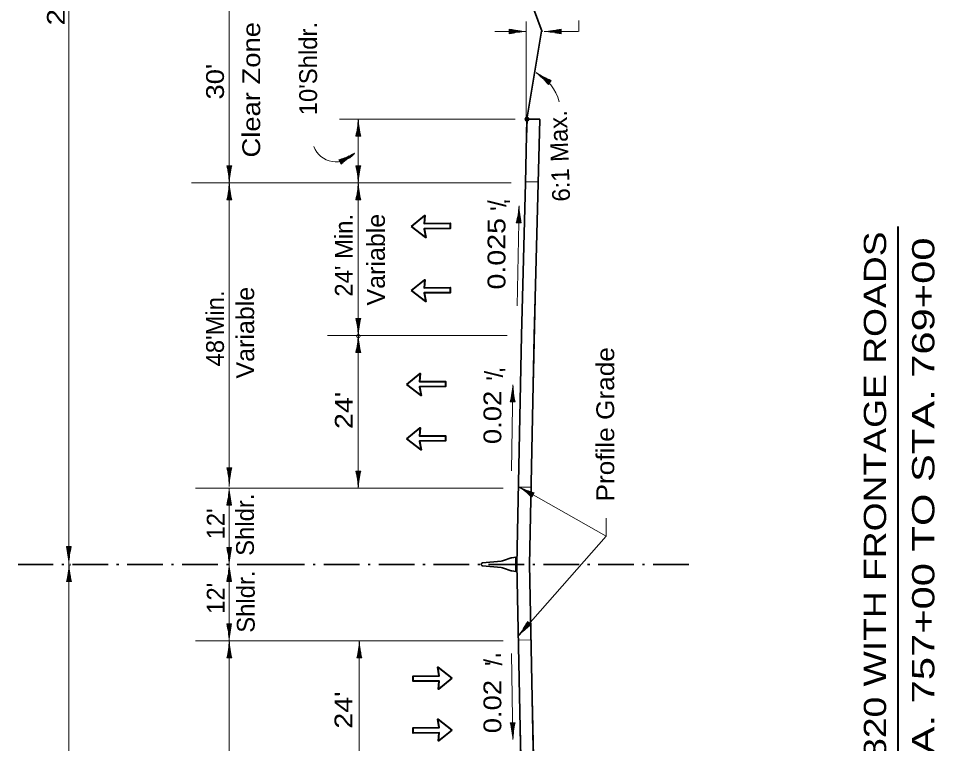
# Model space of a CAD drawing. Extents: x 2363427 to 2368559, y 6957299 to 6980140.
# Drawn here: x 2364656 to 2365376, y 6958931 to 6959501 of the extents above; entities that cross this region are included whole.
import ezdxf
from ezdxf.enums import TextEntityAlignment as Align

# ---------------------------------------------------------------- set-up
doc = ezdxf.new("R2010")
doc.units = 0
doc.header["$LTSCALE"] = 5.6
doc.header["$PDMODE"] = 32
doc.header["$PDSIZE"] = 2.8
doc.linetypes.add('DOT_DASHED', pattern=[7.7, 5, -1.2, 0.3, -1.2])
doc.linetypes.add('LONG_DASHED', pattern=[7.5, 6, -1.5])
for name, color, linetype, lineweight in [('1', 7, 'Continuous', 13), ('3', 7, 'Continuous', 35), ('4', 7, 'Continuous', 13), ('40', 7, 'Continuous', 35), ('6', 7, 'Continuous', 13), ('8', 7, 'Continuous', 13)]:
    doc.layers.add(name, color=color, linetype=linetype, lineweight=lineweight)

msp = doc.modelspace()

# ---------------------------------------------------------------- linework, layer by layer
at = {"layer": '1', "linetype": 'LONG_DASHED'}
msp.add_line((2365055.414, 6959421.319), (2365055.653, 6959421.417), dxfattribs=at)
at = {"layer": '3'}
for p, q in [((2364963.114, 6959774.14), (2365067.63, 6959490.027)), ((2365065.653, 6959421.301), (2365056.156, 6959421.301)), ((2365064.481, 6959371.033), (2365065.65, 6959421.184)), ((2365061.348, 6959251.139), (2365064.48, 6959371.005)), ((2365047.761, 6959071.447), (2365051.351, 6959251.401)), ((2365057.76, 6959071.247), (2365061.35, 6959251.201)), ((2365035.48, 6959074.019), (2365020.776, 6959072.783)), ((2365037.268, 6959074.547), (2365043.382, 6959076.589)), ((2365043.546, 6959076.654), (2365043.556, 6959076.679)), ((2365046.819, 6959077.167), (2365043.556, 6959076.679)), ((2365046.819, 6959077.167), (2365043.753, 6959076.708)), ((2365046.819, 6959077.167), (2365046.819, 6959071.542)), ((2365019.749, 6959071.943), (2365019.749, 6959071.542)), ((2365019.749, 6959071.141), (2365019.749, 6959071.542)), ((2365035.48, 6959069.065), (2365020.776, 6959070.301)), ((2365037.268, 6959068.537), (2365043.382, 6959066.495)), ((2365043.546, 6959066.43), (2365043.556, 6959066.405)), ((2365046.819, 6959065.917), (2365043.556, 6959066.405)), ((2365046.819, 6959065.917), (2365043.753, 6959066.376)), ((2365046.819, 6959065.917), (2365046.819, 6959071.542)), ((2365057.76, 6959071.646), (2365061.35, 6958891.693))]:
    msp.add_line(p, q, dxfattribs=at)
at = {"layer": '3', "lineweight": 13}
for p, q in [((2365067.381, 6959491.559), (2365067.088, 6959490.537)), ((2365046.336, 6959421.447), (2364908.326, 6959421.447)), ((2365043.199, 6959371.447), (2364792.272, 6959371.447)), ((2365040.062, 6959251.447), (2364898.916, 6959251.447)), ((2365036.926, 6959131.447), (2364795.41, 6959131.447)), ((2365036.926, 6959011.447), (2364795.41, 6959011.447))]:
    msp.add_line(p, q, dxfattribs=at)
at = {"layer": '3', "linetype": 'DOT_DASHED'}
for p, q in [((2364855.959, 6959071.447), (2364656.146, 6959071.447)), ((2365182.836, 6959071.447), (2364854.258, 6959071.447))]:
    msp.add_line(p, q, dxfattribs=at)
at = {"layer": '3'}
for points in [[(2365051.351, 6959251.401), (2365054.484, 6959371.267), (2365055.653, 6959421.417), (2365067.088, 6959490.537)], [(2365047.761, 6959071.447), (2365051.351, 6958891.493), (2365054.484, 6958771.627)]]:
    msp.add_lwpolyline(points, dxfattribs=at)
at = {"layer": '3', "lineweight": 13}
for points in [[(2365054.285, 6959372.289), (2365064.582, 6959372.289), (2365065.653, 6959421.301), (2365056.156, 6959421.301)], [(2365049, 6959132.219), (2365058.916, 6959132.218), (2365064.582, 6959372.289), (2365054.285, 6959372.289)], [(2365048.975, 6959011.836), (2365047.721, 6959071.764), (2365049, 6959132.219), (2365058.916, 6959132.218), (2365057.541, 6959071.372), (2365058.919, 6959012.302)], [(2365054.483, 6958770.888), (2365064.398, 6958771.059), (2365058.919, 6959012.302), (2365048.975, 6959011.836)]]:
    msp.add_lwpolyline(points, close=True, dxfattribs=at)
at = {"layer": '3'}
for centre, radius, start, end in [((2365034.98, 6959078.994), 5, 275.73538, 297.22872), ((2365043.93, 6959075.522), 1.2, 98.51269, 117.22516), ((2365020.896, 6959071.59), 1.2, 95.72178, 162.90786), ((2365020.896, 6959071.494), 1.2, 197.09214, 264.27822), ((2365034.98, 6959064.09), 5, 62.77128, 84.26462), ((2365043.93, 6959067.562), 1.2, 242.77484, 261.48731)]:
    msp.add_arc(centre, radius, start, end, dxfattribs=at)
msp.add_point((2365055.653, 6959421.417), dxfattribs=at)
at = {"layer": '4'}
for p, q in [((2365055.102, 6959420.827), (2365055.102, 6959498.291)), ((2365096.47, 6959490.379), (2365096.47, 6959499.023)), ((2365041.791, 6959488.411), (2365041.791, 6959492.241)), ((2365041.791, 6959491.761), (2365044.172, 6959491.761)), ((2365041.791, 6959491.261), (2365046.653, 6959491.261)), ((2365041.791, 6959490.761), (2365050.4, 6959490.761)), ((2365082.53, 6959490.891), (2365075.18, 6959490.891)), ((2365082.53, 6959491.391), (2365078.253, 6959491.391)), ((2365082.53, 6959491.891), (2365080.944, 6959491.891)), ((2365082.53, 6959492.241), (2365082.53, 6959488.411)), ((2365055.102, 6959490.327), (2365030.4, 6959490.327)), ((2365041.791, 6959490.261), (2365054.355, 6959490.261)), ((2365041.791, 6959489.761), (2365049.141, 6959489.761)), ((2365041.791, 6959489.261), (2365046.068, 6959489.261)), ((2365041.791, 6959488.761), (2365043.376, 6959488.761)), ((2365069.218, 6959490.327), (2365095.796, 6959490.327)), ((2365082.53, 6959490.391), (2365069.966, 6959490.391)), ((2365082.53, 6959489.891), (2365073.92, 6959489.891)), ((2365082.53, 6959489.391), (2365077.668, 6959489.391)), ((2365082.53, 6959488.891), (2365080.148, 6959488.891)), ((2365073.662, 6959450.405), (2365063.421, 6959457.685)), ((2365073.372, 6959449.997), (2365066.355, 6959454.985)), ((2365073.952, 6959450.813), (2365067.961, 6959455.071)), ((2365073.082, 6959449.589), (2365069.12, 6959452.407)), ((2365074.241, 6959451.221), (2365070.756, 6959453.697)), ((2365072.793, 6959449.183), (2365070.852, 6959450.563)), ((2365074.734, 6959451.913), (2365072.515, 6959448.791)), ((2365074.531, 6959451.627), (2365073.239, 6959452.545)), ((2364908.086, 6959388.925), (2364910.122, 6959390.161)), ((2364908.346, 6959388.497), (2364912.502, 6959391.019)), ((2364908.605, 6959388.069), (2364915.964, 6959392.537)), ((2364908.864, 6959387.643), (2364919.605, 6959394.161)), ((2364909.124, 6959387.215), (2364915.406, 6959391.029)), ((2364909.824, 6959386.061), (2364907.837, 6959389.335)), ((2364909.384, 6959386.787), (2364913.04, 6959389.007)), ((2364909.643, 6959386.361), (2364910.998, 6959387.183)), ((2365049.461, 6959353.273), (2365047.85, 6959274.651)), ((2365048.624, 6959339.975), (2365048.774, 6959347.323)), ((2365049.123, 6959339.965), (2365049.38, 6959352.527)), ((2365049.623, 6959339.955), (2365049.8, 6959348.563)), ((2365047.274, 6959340.003), (2365051.103, 6959339.925)), ((2365047.624, 6959339.995), (2365047.656, 6959341.581)), ((2365048.124, 6959339.985), (2365048.211, 6959344.261)), ((2365050.123, 6959339.945), (2365050.222, 6959344.805)), ((2365050.623, 6959339.935), (2365050.672, 6959342.315)), ((2365044.629, 6959212.673), (2365043.555, 6959144.957)), ((2365044.353, 6959199.365), (2365044.552, 6959211.927)), ((2365043.353, 6959199.381), (2365043.421, 6959203.657)), ((2365043.853, 6959199.373), (2365043.97, 6959206.721)), ((2365044.853, 6959199.357), (2365044.99, 6959207.965)), ((2365045.352, 6959199.349), (2365045.43, 6959204.211)), ((2365042.503, 6959199.395), (2365046.332, 6959199.333)), ((2365042.853, 6959199.389), (2365042.878, 6959200.973)), ((2365045.852, 6959199.341), (2365045.89, 6959201.723)), ((2365117.773, 6959093.806), (2365048.984, 6959132.754)), ((2365060.413, 6959125.928), (2365049.595, 6959132.317)), ((2365060.667, 6959126.359), (2365053.254, 6959130.737)), ((2365060.158, 6959125.498), (2365053.83, 6959129.235)), ((2365059.904, 6959125.067), (2365056.222, 6959127.242)), ((2365060.922, 6959126.789), (2365056.735, 6959129.262)), ((2365059.65, 6959124.637), (2365058.286, 6959125.442)), ((2365061.176, 6959127.22), (2365059.125, 6959128.432)), ((2365059.471, 6959124.336), (2365061.42, 6959127.633)), ((2365117.773, 6959107.72), (2365117.773, 6959093.806)), ((2365117.773, 6959093.806), (2365048.882, 6959015.234)), ((2365057.505, 6959025.376), (2365049.414, 6959015.764)), ((2365057.122, 6959025.698), (2365051.578, 6959019.111)), ((2365057.887, 6959025.053), (2365053.155, 6959019.431)), ((2365056.74, 6959026.02), (2365053.608, 6959022.3)), ((2365056.357, 6959026.342), (2365054.823, 6959024.52)), ((2365058.27, 6959024.731), (2365055.516, 6959021.46)), ((2365058.92, 6959024.183), (2365055.99, 6959026.651)), ((2365058.652, 6959024.409), (2365057.632, 6959023.197)), ((2365044.629, 6958933.771), (2365043.555, 6959001.489)), ((2365042.503, 6958947.051), (2365046.332, 6958947.111)), ((2365042.853, 6958947.057), (2365042.878, 6958945.471)), ((2365043.353, 6958947.065), (2365043.421, 6958942.789)), ((2365043.853, 6958947.073), (2365043.97, 6958939.723)), ((2365044.353, 6958947.081), (2365044.552, 6958934.517)), ((2365044.853, 6958947.089), (2365044.99, 6958938.479)), ((2365045.352, 6958947.097), (2365045.43, 6958942.235)), ((2365045.852, 6958947.105), (2365045.89, 6958944.723))]:
    msp.add_line(p, q, dxfattribs=at)
at = {"layer": '4', "lineweight": 40}
msp.add_line((2365347.244, 6958874.931), (2365347.244, 6959337.074), dxfattribs=at)
at = {"layer": '4'}
for centre, radius, start, end in [((2365058.685, 6959562.45), 72.212, 256.47039, 267.15644), ((2365065.636, 6959562.45), 72.212, 272.84356, 283.52961), ((2365058.685, 6959418.203), 72.212, 92.84356, 103.52961), ((2365065.636, 6959418.203), 72.212, 76.47039, 87.15644), ((2365046.984, 6959426.793), 34.94, 13.44028, 63.14536), ((2365101.642, 6959518.925), 72.212, 237.43652, 248.12257), ((2365018.068, 6959401.355), 72.212, 41.06336, 51.74941), ((2364905.832, 6959406.596), 18.823, 200.84978, 319.74384), ((2364885.845, 6959458.117), 72.212, 287.73061, 298.41666), ((2364960.699, 6959334.812), 72.212, 124.10378, 134.78983), ((2364977.426, 6959358.331), 72.212, 345.29652, 355.98257), ((2365121.643, 6959355.376), 72.212, 181.66968, 192.35573), ((2364972.571, 6959217.399), 72.212, 345.56175, 356.2478), ((2365116.8, 6959215.112), 72.212, 181.93492, 192.62097), ((2365082.578, 6959196.676), 72.212, 242.27611, 252.96216), ((2365009.221, 6959072.475), 72.212, 45.90294, 56.58899), ((2364991.401, 6959058.944), 72.212, 322.74962, 333.43567), ((2365101.749, 6958966.043), 72.212, 126.37646, 137.06251), ((2364972.571, 6958929.046), 72.212, 3.7522, 14.43825), ((2365116.8, 6958931.333), 72.212, 167.37903, 178.06508)]:
    msp.add_arc(centre, radius, start, end, dxfattribs=at)
at = {"layer": '40'}
for p, q in [((2364974.856, 6959339.363), (2364995.36, 6959339.557)), ((2364974.856, 6959288.911), (2364995.36, 6959289.106)), ((2364971.216, 6959215.175), (2364991.721, 6959215.369)), ((2364971.216, 6959172.485), (2364991.721, 6959172.68)), ((2364986.774, 6958979.863), (2364966.27, 6958979.667)), ((2364986.774, 6958939.113), (2364966.27, 6958938.919))]:
    msp.add_line(p, q, dxfattribs=at)
for points in [[(2364974.856, 6959339.363), (2364975.388, 6959345.677), (2364965, 6959337.143), (2364976.1, 6959328.54), (2364974.893, 6959335.267)], [(2364974.893, 6959335.267), (2364995.398, 6959335.463), (2364995.36, 6959339.557)], [(2364974.856, 6959288.911), (2364975.388, 6959295.226), (2364965, 6959286.691), (2364976.1, 6959278.089), (2364974.893, 6959284.816)], [(2364974.893, 6959284.816), (2364995.398, 6959285.011), (2364995.36, 6959289.106)], [(2364971.216, 6959215.175), (2364971.748, 6959221.489), (2364961.361, 6959212.955), (2364972.461, 6959204.352), (2364971.254, 6959211.079)], [(2364971.254, 6959211.079), (2364991.758, 6959211.275), (2364991.721, 6959215.369)], [(2364971.216, 6959172.485), (2364971.748, 6959178.8), (2364961.361, 6959170.265), (2364972.461, 6959161.663), (2364971.254, 6959168.39)], [(2364971.254, 6959168.39), (2364991.758, 6959168.585), (2364991.721, 6959172.68)], [(2364986.774, 6958979.863), (2364986.242, 6958973.547), (2364996.63, 6958982.083), (2364985.53, 6958990.685), (2364986.737, 6958983.957)], [(2364986.737, 6958983.957), (2364966.232, 6958983.763), (2364966.27, 6958979.667)], [(2364986.774, 6958939.113), (2364986.242, 6958932.799), (2364996.63, 6958941.333), (2364985.53, 6958949.936), (2364986.737, 6958943.209)], [(2364986.737, 6958943.209), (2364966.232, 6958943.013), (2364966.27, 6958938.919)]]:
    msp.add_lwpolyline(points, dxfattribs=at)
at = {"layer": '6'}
for p, q in [((2364695.798, 6959070.731), (2364695.798, 6960071.447)), ((2364923.238, 6959408.135), (2364923.238, 6959420.699)), ((2364922.238, 6959408.135), (2364922.238, 6959412.997)), ((2364922.738, 6959408.135), (2364922.738, 6959416.745)), ((2364923.738, 6959408.135), (2364923.738, 6959415.485)), ((2364924.238, 6959408.135), (2364924.238, 6959412.411)), ((2364925.088, 6959408.135), (2364921.258, 6959408.135)), ((2364921.738, 6959408.135), (2364921.738, 6959410.517)), ((2364924.738, 6959408.135), (2364924.738, 6959409.72)), ((2364819.941, 6959384.73), (2364823.771, 6959384.73)), ((2364820.291, 6959384.73), (2364820.291, 6959383.145)), ((2364820.791, 6959384.73), (2364820.791, 6959380.453)), ((2364821.291, 6959384.73), (2364821.291, 6959377.38)), ((2364821.791, 6959384.73), (2364821.791, 6959372.166)), ((2364822.291, 6959384.73), (2364822.291, 6959376.121)), ((2364822.791, 6959384.73), (2364822.791, 6959379.868)), ((2364823.291, 6959384.73), (2364823.291, 6959382.349)), ((2364921.258, 6959384.73), (2364925.088, 6959384.73)), ((2364921.608, 6959384.73), (2364921.608, 6959383.145)), ((2364922.108, 6959384.73), (2364922.108, 6959380.453)), ((2364922.608, 6959384.73), (2364922.608, 6959377.38)), ((2364923.108, 6959384.73), (2364923.108, 6959372.166)), ((2364923.608, 6959384.73), (2364923.608, 6959376.121)), ((2364924.108, 6959384.73), (2364924.108, 6959379.868)), ((2364924.608, 6959384.73), (2364924.608, 6959382.349)), ((2364821.921, 6959358.107), (2364821.921, 6959370.671)), ((2364923.238, 6959358.107), (2364923.238, 6959370.671)), ((2364820.921, 6959358.107), (2364820.921, 6959362.969)), ((2364821.421, 6959358.107), (2364821.421, 6959366.717)), ((2364822.421, 6959358.107), (2364822.421, 6959365.457)), ((2364822.921, 6959358.107), (2364822.921, 6959362.383)), ((2364922.238, 6959358.107), (2364922.238, 6959362.969)), ((2364922.738, 6959358.107), (2364922.738, 6959366.717)), ((2364923.738, 6959358.107), (2364923.738, 6959365.457)), ((2364924.238, 6959358.107), (2364924.238, 6959362.383)), ((2364823.771, 6959358.107), (2364819.941, 6959358.107)), ((2364820.421, 6959358.107), (2364820.421, 6959360.489)), ((2364823.421, 6959358.107), (2364823.421, 6959359.692)), ((2364925.088, 6959358.107), (2364921.258, 6959358.107)), ((2364921.738, 6959358.107), (2364921.738, 6959360.489)), ((2364924.738, 6959358.107), (2364924.738, 6959359.692)), ((2364921.258, 6959264.758), (2364925.088, 6959264.758)), ((2364921.608, 6959264.758), (2364921.608, 6959263.173)), ((2364922.108, 6959264.758), (2364922.108, 6959260.481)), ((2364922.608, 6959264.758), (2364922.608, 6959257.408)), ((2364923.108, 6959264.758), (2364923.108, 6959252.194)), ((2364923.608, 6959264.758), (2364923.608, 6959256.149)), ((2364924.108, 6959264.758), (2364924.108, 6959259.896)), ((2364924.608, 6959264.758), (2364924.608, 6959262.377)), ((2364922.738, 6959238.135), (2364922.738, 6959246.745)), ((2364923.173, 6959252.075), (2364923.173, 6959252.705)), ((2364923.173, 6959131.503), (2364923.173, 6959251.447)), ((2364923.238, 6959238.135), (2364923.238, 6959250.699)), ((2364921.738, 6959238.135), (2364921.738, 6959240.517)), ((2364922.238, 6959238.135), (2364922.238, 6959242.997)), ((2364923.738, 6959238.135), (2364923.738, 6959245.485)), ((2364924.238, 6959238.135), (2364924.238, 6959242.411)), ((2364924.738, 6959238.135), (2364924.738, 6959239.72)), ((2364925.088, 6959238.135), (2364921.258, 6959238.135)), ((2364819.941, 6959147.33), (2364823.771, 6959147.33)), ((2364820.291, 6959147.33), (2364820.291, 6959145.745)), ((2364820.791, 6959147.33), (2364820.791, 6959143.053)), ((2364821.291, 6959147.33), (2364821.291, 6959139.98)), ((2364821.791, 6959147.33), (2364821.791, 6959134.766)), ((2364822.291, 6959147.33), (2364822.291, 6959138.721)), ((2364822.791, 6959147.33), (2364822.791, 6959142.468)), ((2364823.291, 6959147.33), (2364823.291, 6959144.949)), ((2364921.258, 6959144.814), (2364925.088, 6959144.814)), ((2364921.608, 6959144.814), (2364921.608, 6959143.229)), ((2364922.108, 6959144.814), (2364922.108, 6959140.537)), ((2364922.608, 6959144.814), (2364922.608, 6959137.464)), ((2364923.108, 6959144.814), (2364923.108, 6959132.25)), ((2364923.608, 6959144.814), (2364923.608, 6959136.205)), ((2364924.108, 6959144.814), (2364924.108, 6959139.952)), ((2364924.608, 6959144.814), (2364924.608, 6959142.433)), ((2364821.856, 6959132.733), (2364821.856, 6959134.019)), ((2364821.332, 6959118.135), (2364821.332, 6959126.745)), ((2364821.832, 6959118.135), (2364821.832, 6959130.699)), ((2364822.332, 6959118.135), (2364822.332, 6959125.485)), ((2364823.682, 6959118.135), (2364819.852, 6959118.135)), ((2364820.332, 6959118.135), (2364820.332, 6959120.517)), ((2364820.832, 6959118.135), (2364820.832, 6959122.997)), ((2364822.832, 6959118.135), (2364822.832, 6959122.411)), ((2364823.332, 6959118.135), (2364823.332, 6959119.721)), ((2364693.882, 6959085.449), (2364697.712, 6959085.449)), ((2364694.232, 6959085.449), (2364694.232, 6959083.863)), ((2364694.732, 6959085.449), (2364694.732, 6959081.173)), ((2364695.232, 6959085.449), (2364695.232, 6959078.099)), ((2364695.732, 6959085.449), (2364695.732, 6959072.885)), ((2364696.232, 6959085.449), (2364696.232, 6959076.839)), ((2364696.732, 6959085.449), (2364696.732, 6959080.587)), ((2364697.232, 6959085.449), (2364697.232, 6959083.067)), ((2364819.852, 6959084.759), (2364823.682, 6959084.759)), ((2364820.202, 6959084.759), (2364820.202, 6959083.173)), ((2364820.702, 6959084.759), (2364820.702, 6959080.481)), ((2364821.202, 6959084.759), (2364821.202, 6959077.409)), ((2364821.702, 6959084.759), (2364821.702, 6959072.195)), ((2364822.202, 6959084.759), (2364822.202, 6959076.149)), ((2364822.702, 6959084.759), (2364822.702, 6959079.897)), ((2364823.202, 6959084.759), (2364823.202, 6959082.377)), ((2364695.498, 6959058.135), (2364695.498, 6959066.745)), ((2364695.934, 6958071.447), (2364695.934, 6959071.447)), ((2364695.998, 6959058.135), (2364695.998, 6959070.699)), ((2364696.784, 6959070.731), (2364696.784, 6959071.843)), ((2364821.332, 6959058.135), (2364821.332, 6959066.745)), ((2364821.832, 6959058.135), (2364821.832, 6959070.699)), ((2364694.498, 6959058.135), (2364694.498, 6959060.517)), ((2364694.998, 6959058.135), (2364694.998, 6959062.997)), ((2364696.498, 6959058.135), (2364696.498, 6959065.485)), ((2364696.998, 6959058.135), (2364696.998, 6959062.411)), ((2364697.498, 6959058.135), (2364697.498, 6959059.72)), ((2364820.332, 6959058.135), (2364820.332, 6959060.517)), ((2364820.832, 6959058.135), (2364820.832, 6959062.997)), ((2364822.332, 6959058.135), (2364822.332, 6959065.485)), ((2364822.832, 6959058.135), (2364822.832, 6959062.411)), ((2364823.332, 6959058.135), (2364823.332, 6959059.721)), ((2364697.848, 6959058.135), (2364694.018, 6959058.135)), ((2364823.682, 6959058.135), (2364819.852, 6959058.135)), ((2364819.852, 6959024.759), (2364823.682, 6959024.759)), ((2364820.202, 6959024.759), (2364820.202, 6959023.173)), ((2364820.702, 6959024.759), (2364820.702, 6959020.481)), ((2364821.202, 6959024.759), (2364821.202, 6959017.409)), ((2364821.702, 6959024.759), (2364821.702, 6959012.195)), ((2364822.202, 6959024.759), (2364822.202, 6959016.149)), ((2364822.702, 6959024.759), (2364822.702, 6959019.897)), ((2364823.202, 6959024.759), (2364823.202, 6959022.377)), ((2364821.862, 6958771.425), (2364821.862, 6959011.447)), ((2364821.927, 6958998.135), (2364821.927, 6959010.699)), ((2364923.994, 6958782.647), (2364923.994, 6959011.447)), ((2364924.06, 6958998.135), (2364924.06, 6959010.699)), ((2364820.927, 6958998.135), (2364820.927, 6959002.997)), ((2364821.427, 6958998.135), (2364821.427, 6959006.745)), ((2364822.427, 6958998.135), (2364822.427, 6959005.485)), ((2364822.927, 6958998.135), (2364822.927, 6959002.411)), ((2364923.06, 6958998.135), (2364923.06, 6959002.997)), ((2364923.56, 6958998.135), (2364923.56, 6959006.745)), ((2364924.56, 6958998.135), (2364924.56, 6959005.485)), ((2364925.06, 6958998.135), (2364925.06, 6959002.411)), ((2364823.777, 6958998.135), (2364819.947, 6958998.135)), ((2364820.427, 6958998.135), (2364820.427, 6959000.517)), ((2364823.427, 6958998.135), (2364823.427, 6958999.72)), ((2364925.91, 6958998.135), (2364922.08, 6958998.135)), ((2364922.56, 6958998.135), (2364922.56, 6959000.517)), ((2364925.56, 6958998.135), (2364925.56, 6958999.72))]:
    msp.add_line(p, q, dxfattribs=at)
for points in [[(2364821.856, 6959134.019), (2364821.856, 6959371.419), (2364821.856, 6959521.447)], [(2364923.173, 6959250.845), (2364923.173, 6959251.447), (2364923.173, 6959371.419), (2364923.173, 6959421.447)], [(2364821.767, 6959011.447), (2364821.767, 6959071.447), (2364821.767, 6959131.447)]]:
    msp.add_lwpolyline(points, dxfattribs=at)
for centre, start, end in [((2364851.049, 6959425.029), 346.47039, 357.15644), ((2364995.297, 6959425.029), 182.84356, 193.52961), ((2364749.732, 6959367.836), 2.84356, 13.52961), ((2364893.98, 6959367.836), 166.47039, 177.15644), ((2364851.049, 6959367.836), 2.84356, 13.52961), ((2364995.297, 6959367.836), 166.47039, 177.15644), ((2364749.732, 6959375.001), 346.47039, 357.15644), ((2364893.98, 6959375.001), 182.84356, 193.52961), ((2364851.049, 6959375.001), 346.47039, 357.15644), ((2364995.297, 6959375.001), 182.84356, 193.52961), ((2364851.049, 6959247.864), 2.84356, 13.52961), ((2364995.297, 6959247.864), 166.47039, 177.15644), ((2364851.049, 6959255.029), 346.47039, 357.15644), ((2364995.297, 6959255.029), 182.84356, 193.52961), ((2364749.732, 6959130.436), 2.84356, 13.52961), ((2364893.98, 6959130.436), 166.47039, 177.15644), ((2364851.049, 6959127.92), 2.84356, 13.52961), ((2364995.297, 6959127.92), 166.47039, 177.15644), ((2364749.643, 6959135.029), 346.47039, 357.15644), ((2364893.891, 6959135.029), 182.84356, 193.52961), ((2364623.674, 6959068.555), 2.84356, 13.52961), ((2364767.921, 6959068.555), 166.47039, 177.15644), ((2364749.643, 6959067.864), 2.84356, 13.52961), ((2364893.891, 6959067.864), 166.47039, 177.15644), ((2364623.81, 6959075.029), 346.47039, 357.15644), ((2364768.057, 6959075.029), 182.84356, 193.52961), ((2364749.643, 6959075.029), 346.47039, 357.15644), ((2364893.891, 6959075.029), 182.84356, 193.52961), ((2364749.643, 6959007.864), 2.84356, 13.52961), ((2364893.891, 6959007.864), 166.47039, 177.15644), ((2364749.738, 6959015.029), 346.47039, 357.15644), ((2364893.986, 6959015.029), 182.84356, 193.52961), ((2364851.871, 6959015.029), 346.47039, 357.15644), ((2364996.118, 6959015.029), 182.84356, 193.52961)]:
    msp.add_arc(centre, 72.212, start, end, dxfattribs=at)
msp.add_point((2364923.173, 6959250.845), dxfattribs=at)
at = {"layer": '8', "lineweight": 40}
for points in [[(2364965, 6959337.143), (2364975.388, 6959345.677), (2364974.856, 6959339.363), (2364995.36, 6959339.557), (2364995.398, 6959335.463), (2364974.893, 6959335.267), (2364976.1, 6959328.54)], [(2364965, 6959286.691), (2364975.388, 6959295.226), (2364974.856, 6959288.911), (2364995.36, 6959289.106), (2364995.398, 6959285.011), (2364974.893, 6959284.816), (2364976.1, 6959278.089)], [(2364961.361, 6959212.955), (2364971.748, 6959221.489), (2364971.216, 6959215.175), (2364991.721, 6959215.369), (2364991.758, 6959211.275), (2364971.254, 6959211.079), (2364972.461, 6959204.352)], [(2364961.361, 6959170.265), (2364971.748, 6959178.8), (2364971.216, 6959172.485), (2364991.721, 6959172.68), (2364991.758, 6959168.585), (2364971.254, 6959168.39), (2364972.461, 6959161.663)], [(2364996.63, 6958982.083), (2364986.242, 6958973.547), (2364986.774, 6958979.863), (2364966.27, 6958979.667), (2364966.232, 6958983.763), (2364986.737, 6958983.957), (2364985.53, 6958990.685)], [(2364996.63, 6958941.333), (2364986.242, 6958932.799), (2364986.774, 6958939.113), (2364966.27, 6958938.919), (2364966.232, 6958943.013), (2364986.737, 6958943.209), (2364985.53, 6958949.936)]]:
    msp.add_lwpolyline(points, close=True, dxfattribs=at)

# ---------------------------------------------------------------- texts
at = {"layer": '4'}
for s, height, width, p in [("200'", 14, 1.25, (2364692.658, 6959516.82)), ('Clear Zone', 14, 1.15, (2364846.102, 6959444.52)), ("30'", 14, 1.15, (2364817.662, 6959450.889)), ('Variable', 14, 1.05, (2364944.062, 6959311.019)), ('0.025', 14, 1.2, (2365038.744, 6959315.644)), ('IH 820 WITH FRONTAGE ROADS', 17.5, 1.25, (2365337.76, 6959107.242)), ('STA. 757+00 TO STA. 769+00', 17.5, 1.4, (2365375.66, 6959104.418)), ('Variable', 14, 1.05, (2364841.362, 6959253.611)), ('Profile Grade', 14, 1.1, (2365124.161, 6959181.605)), ("24'", 14, 1.2, (2364918.782, 6959192.552)), ('0.02', 14, 1.15, (2365035.522, 6959187.022)), ('0.02', 14, 1.15, (2365035.522, 6958959.768)), ("24'", 14, 1.2, (2364918.519, 6958957.069))]:
    msp.add_text(s, height=height, rotation=90, dxfattribs=dict(at, width=width)).set_placement(p, align=Align.CENTER)
for s, rotation, p in [("10'Shldr.", 90, (2364890.786, 6959461.14)), ('6:1 Max.', 92.174, (2365088.254, 6959392.788)), ('/', 90, (2365039.338, 6959355.047)), ("'", 90, (2365051.876, 6959356.704)), ("'", 90, (2365040.906, 6959351.121)), ("24' Min.", 90, (2364918.782, 6959314.435)), ("48'Min.", 90, (2364817.662, 6959256.971)), ("'", 90, (2365048.218, 6959224.372)), ('/', 90, (2365036.726, 6959221.039)), ("'", 90, (2365037.772, 6959217.672)), ('Shldr.', 90, (2364841.2, 6959102.726)), ("12'", 90, (2364818.199, 6959103.324)), ('Shldr.', 90, (2364841.822, 6959042.272)), ("12'", 90, (2364818.199, 6959044.862)), ('/', 90, (2365036.06, 6958994.639)), ("'", 90, (2365036.596, 6958993.516)), ("'", 90, (2365044.958, 6959000.047))]:
    msp.add_text(s, height=14, rotation=rotation, dxfattribs=at).set_placement(p, align=Align.CENTER)

doc.saveas('drawing.dxf')
